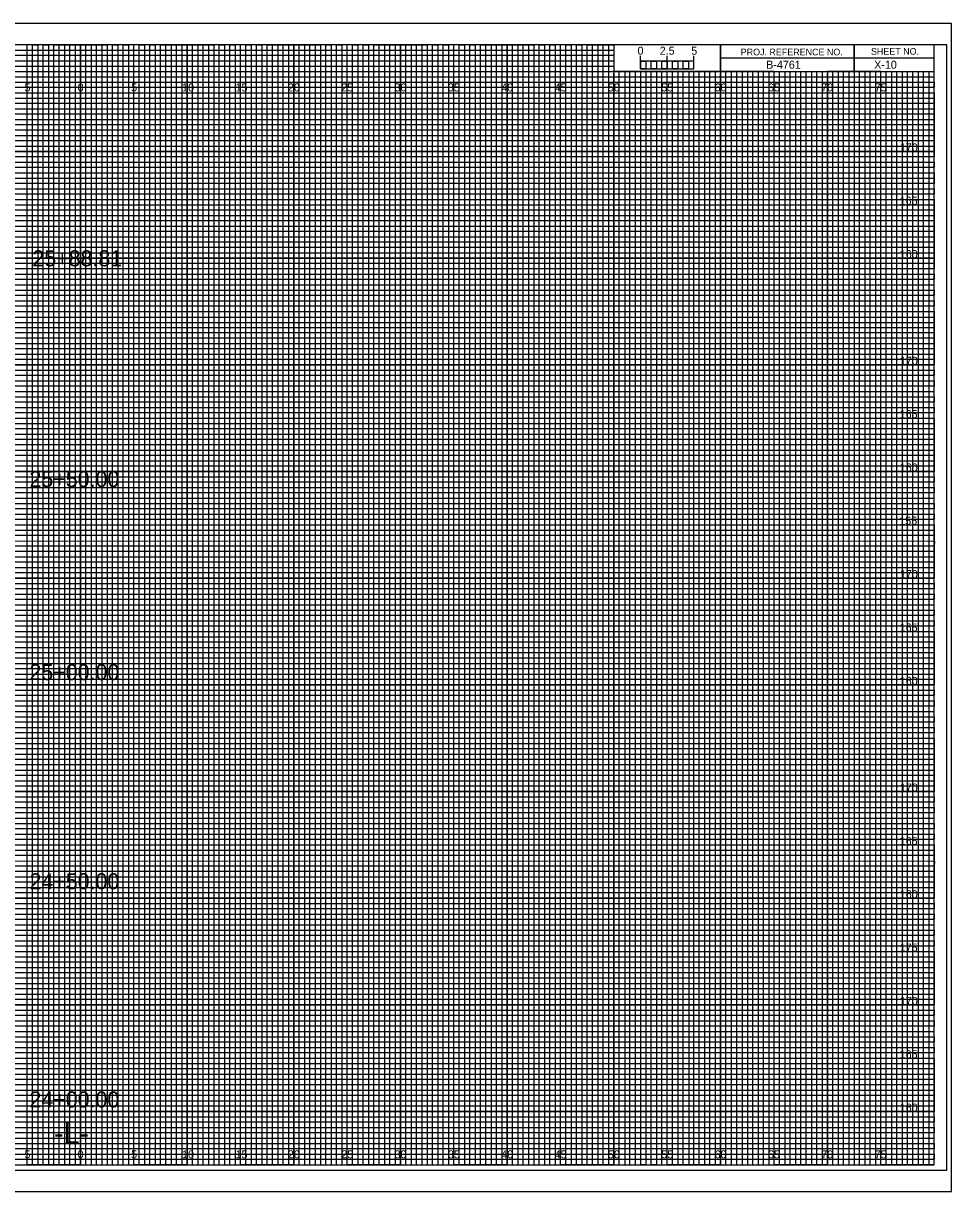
# Model space of a CAD drawing. Extents: x -7 to 162, y 878 to 987.
# Drawn here: x 74.6 to 161.7, y 877.5 to 987 of the extents above; entities that cross this region are included whole.
import ezdxf

# ---------------------------------------------------------------- set-up
doc = ezdxf.new("R2010")
doc.units = 0
for name, color, linetype in [('Prop XS Alignment Label', 7, 'Continuous'), ('Prop XS Bar Scale Labels', 7, 'Continuous'), ('Prop XS Elevation Labels', 7, 'Continuous'), ('Prop XS Offset Labels', 7, 'Continuous'), ('Prop XS Project Number', 7, 'Continuous'), ('Prop XS Sheet Number', 7, 'Continuous'), ('Prop XS Station Labels', 7, 'Continuous'), ('Sheet Cross Section CELL', 7, 'Continuous'), ('Sheet Cross Section Grid Major CELL', 7, 'Continuous'), ('Sheet Cross Section Grid Middle CELL', 7, 'Continuous'), ('Sheet Cross Section Grid Minor 1 CELL', 7, 'Continuous'), ('Sheet Cross Section Grid Minor 2 CELL', 7, 'Continuous'), ('Sheet Cross Section Scale CELL', 7, 'Continuous'), ('Sheet Cutting Line CELL', 7, 'Continuous'), ('Sheet DOT Grid CELL', 7, 'Continuous'), ('Sheet Plot Border Inside CELL', 7, 'Continuous'), ('Sheet Plot Border Outside CELL', 7, 'Continuous')]:
    doc.layers.add(name, color=color, linetype=linetype)

msp = doc.modelspace()

# ---------------------------------------------------------------- linework, layer by layer
at = {"layer": 'Sheet Cross Section CELL'}
for p, q in [((152.5, 985), (152.5, 982.5)), ((152.5, 982.5), (152.5, 985)), ((160, 983.75), (140, 983.75)), ((140, 983.75), (140, 982.5)), ((140, 982.5), (160, 982.5))]:
    msp.add_line(p, q, dxfattribs=at)
for points in [[(160, 985), (0, 985), (0, 880), (160, 880)], [(140, 985), (130, 985), (130, 982.51), (140, 982.51)], [(160, 985), (140, 985), (140, 982.5), (160, 982.5)]]:
    msp.add_lwpolyline(points, close=True, dxfattribs=at)
at = {"layer": 'Sheet Cross Section Grid Major CELL'}
for p, q in [((75, 985), (70, 985)), ((75, 880), (75, 985)), ((85, 985), (80, 985)), ((80, 985), (80, 880)), ((85, 880), (85, 985)), ((95, 985), (90, 985)), ((90, 985), (90, 880)), ((95, 880), (95, 985)), ((105, 985), (100, 985)), ((100, 985), (100, 880)), ((105, 880), (105, 985)), ((115, 985), (110, 985)), ((110, 985), (110, 880)), ((115, 880), (115, 985)), ((125, 985), (120, 985)), ((120, 985), (120, 880)), ((125, 880), (125, 985)), ((130, 985), (130, 880)), ((135, 880), (135, 982.5)), ((145, 982.5), (140, 982.5)), ((140, 982.5), (140, 880)), ((145, 880), (145, 982.5)), ((155, 982.5), (150, 982.5)), ((150, 982.5), (150, 880)), ((155, 880), (155, 982.5)), ((80, 880), (75, 880)), ((90, 880), (85, 880)), ((100, 880), (95, 880)), ((110, 880), (105, 880)), ((120, 880), (115, 880)), ((130, 880), (125, 880)), ((140, 880), (135, 880)), ((150, 880), (145, 880)), ((160, 880), (155, 880)), ((160, 880), (160, 880))]:
    msp.add_line(p, q, dxfattribs=at)
for points in [[(0, 980), (160, 980), (160, 975), (0, 975)], [(0, 970), (160, 970), (160, 965), (0, 965)], [(0, 960), (160, 960), (160, 955), (0, 955)], [(0, 950), (160, 950), (160, 945), (0, 945)], [(0, 940), (160, 940), (160, 935), (0, 935)], [(0, 930), (160, 930), (160, 925), (0, 925)], [(0, 920), (160, 920), (160, 915), (0, 915)], [(0, 910), (160, 910), (160, 905), (0, 905)], [(0, 900), (160, 900), (160, 895), (0, 895)], [(0, 890), (160, 890), (160, 885), (0, 885)]]:
    msp.add_lwpolyline(points, dxfattribs=at)
at = {"layer": 'Sheet Cross Section Grid Middle CELL'}
for points in [[(72.5, 880), (77.5, 880), (77.5, 985), (82.5, 985), (82.5, 880), (87.5, 880), (87.5, 985), (92.5, 985), (92.5, 880), (97.5, 880), (97.5, 985), (102.5, 985), (102.5, 880), (107.5, 880), (107.5, 985), (112.5, 985), (112.5, 880), (117.5, 880), (117.5, 985), (122.5, 985), (122.5, 880), (127.5, 880), (127.5, 985), (129.97, 985), (130, 985), (130, 982.5), (132.5, 982.5), (132.5, 880), (137.5, 880), (137.5, 982.5), (142.5, 982.5), (142.5, 880), (147.5, 880), (147.5, 982.5), (152.5, 982.5), (152.5, 880), (157.5, 880), (157.5, 982.5)], [(0, 982.5), (137.5, 982.5)], [(0, 972.5), (160, 972.5), (160, 977.5), (0, 977.5)], [(0, 962.5), (160, 962.5), (160, 967.5), (0, 967.5)], [(0, 952.5), (160, 952.5), (160, 957.5), (0, 957.5)], [(0, 942.5), (160, 942.5), (160, 947.5), (0, 947.5)], [(0, 932.5), (160, 932.5), (160, 937.5), (0, 937.5)], [(0, 922.5), (160, 922.5), (160, 927.5), (0, 927.5)], [(0, 912.5), (160, 912.5), (160, 917.5), (0, 917.5)], [(0, 902.5), (160, 902.5), (160, 907.5), (0, 907.5)], [(0, 892.5), (160, 892.5), (160, 897.5), (0, 897.5)], [(0, 882.5), (160, 882.5), (160, 887.5), (0, 887.5)]]:
    msp.add_lwpolyline(points, dxfattribs=at)
at = {"layer": 'Sheet Cross Section Grid Minor 1 CELL'}
for p, q in [((0, 984.5), (130, 984.5)), ((130, 984.5), (130, 983.99)), ((130, 983.99), (0, 983.99)), ((0, 983.5), (130, 983.5)), ((130, 983.5), (130, 982.95)), ((130, 982.95), (0, 982.95)), ((0, 982), (160, 982))]:
    msp.add_line(p, q, dxfattribs=at)
for points in [[(0, 981.5), (135, 981.5), (160, 981.5), (160, 981), (0, 981)], [(0, 980.5), (160, 980.5), (160, 979.5), (0, 979.5)], [(0, 979), (160, 979), (160, 978.5), (0, 978.49)], [(0, 978), (160, 978), (160, 977), (0, 977)], [(0, 976.5), (160, 976.5), (160, 976), (0, 976)], [(0, 975.5), (160, 975.5), (160, 974.5), (0, 974.5)], [(0, 974), (160, 974), (160, 973.5), (0, 973.5)], [(0, 973), (160, 973), (160, 972), (0, 972)], [(0, 971.5), (160, 971.5), (160, 971), (0, 971)], [(0, 970.5), (160, 970.5), (160, 969.5), (0, 969.5)], [(0, 969), (160, 969), (160, 968.5), (0, 968.5)], [(0, 968), (160, 968), (160, 966.98), (160, 966.5), (160, 966), (0, 966)], [(0, 967), (160, 967), (160, 966.5), (0, 966.5)], [(0, 965.5), (160, 965.5), (160, 964.5), (0, 964.51)], [(0, 964.51), (160, 964.5), (160, 964), (0, 964)], [(0, 963.5), (160, 963.5), (160, 963), (0, 963)], [(0, 962), (160, 962), (160, 961.5), (0, 961.5)], [(0, 961), (160, 961), (160, 960.5), (0, 960.5)], [(-0.04, 959.45), (160, 959.45), (160, 958.94), (-0.04, 958.94)], [(0, 958.5), (160, 958.5), (160, 958), (0, 958)], [(0, 957), (160, 957), (160, 956.5), (0, 956.5)], [(0, 956), (160, 956), (160, 955.5), (0, 955.5)], [(0, 954.5), (160, 954.5), (160, 954), (0, 954)], [(0, 953.5), (160, 953.5), (160, 953), (0, 953)], [(0, 952), (160, 952), (160, 951.5), (0, 951.5)], [(0, 951), (160, 951), (160, 950.5), (0, 950.5)], [(0, 949.5), (160, 949.5), (160, 948.99), (0, 949)], [(0, 948.5), (160, 948.5), (160, 948), (0, 948)], [(0, 947), (160, 947), (160, 946.5), (0, 946.5)], [(0, 946), (160, 946), (160, 945.5), (0, 945.5)], [(0, 944.5), (160, 944.5), (160, 944), (0, 944)], [(0, 943.5), (160, 943.5), (160, 943), (0, 943)], [(0, 942), (160, 942), (160, 941.5), (0, 941.5)], [(0, 941), (160, 941), (160, 940.5), (0, 940.5)], [(0, 939.5), (160, 939.5), (160, 939), (0, 939)], [(0, 938.5), (160.03, 938.46), (160, 938), (0, 938)], [(0, 937), (160, 937), (160, 936.5), (0, 936.5)], [(0, 936), (160, 936), (160, 935.5), (0, 935.5)], [(0, 934.5), (160, 934.5), (160, 934), (0, 934)], [(0, 933.5), (160, 933.5), (160, 933), (0, 933)], [(0, 932), (160, 932), (160, 931.5), (0, 931.5)], [(0, 931), (160, 931), (160, 930.5), (0, 930.5)], [(0, 929.5), (160, 929.5), (160, 929), (0, 929)], [(0, 928.5), (160, 928.5), (160, 928), (0, 928)], [(0, 927), (160, 927), (160, 926.5), (0, 926.5)], [(0, 926), (160, 926), (160, 925.5), (0, 925.5)], [(0, 924.5), (160, 924.5), (160, 924), (0, 924)], [(0, 923.5), (160, 923.5), (160, 923), (0, 923)], [(0, 922), (160, 922), (160, 921.5), (0, 921.5)], [(0, 921), (160, 921), (160, 920.5), (0, 920.5)], [(0, 919.5), (160, 919.5), (160, 918.99), (0, 919)], [(0, 918.5), (160, 918.5), (160, 918), (0, 918)], [(0, 917), (160, 917), (160, 916.5), (0, 916.5)], [(0, 916), (160, 916), (160, 915.5), (0, 915.5)], [(0, 914.5), (160, 914.5), (160, 914), (0, 914)], [(0, 913.5), (160, 913.5), (160, 913), (0, 913)], [(0, 912), (160, 912), (160, 911.5), (0, 911.5)], [(0, 911), (160, 911), (160, 910.5), (0, 910.5)], [(0, 909.5), (160, 909.5), (160, 909), (0, 909)], [(0, 908.5), (160.03, 908.46), (160, 908), (0, 908)], [(0, 907), (160, 907), (160, 906.5), (0, 906.5)], [(0, 906), (160, 906), (160, 905.5), (0, 905.5)], [(0, 904.5), (160, 904.5), (160, 904), (0, 904)], [(0, 903.5), (160, 903.5), (160, 903), (0, 903)], [(0, 902), (160, 902), (160, 901.5), (0, 901.5)], [(0, 901), (160, 901), (160, 900.5), (0, 900.5)], [(0, 899.5), (160, 899.5), (160, 899), (0, 899)], [(0, 898.5), (160, 898.5), (160, 898), (0, 898)], [(0, 897), (160, 897), (160, 896.5), (0, 896.5)], [(0, 896), (160, 896), (160, 895.5), (0, 895.5)], [(0, 894.5), (160, 894.5), (160, 894), (0, 894)], [(0, 893.5), (160, 893.5), (160, 893), (0, 893)], [(0, 892), (160, 892), (160, 891.5), (0, 891.5)], [(0, 891), (160, 891), (160, 890.5), (0, 890.5)], [(0, 889.5), (160, 889.5), (160, 889), (0, 889)], [(0, 888.5), (160, 888.5), (160, 888), (0, 888)], [(0, 887), (160, 887), (160, 886.5), (0, 886.5)], [(0, 886), (160, 886), (160, 885.5), (0, 885.5)], [(0, 884.5), (160, 884.5), (160, 884), (0, 884)], [(0, 883.5), (160, 883.5), (160, 883), (0, 883)], [(0, 882), (160, 882), (160, 881.5), (0, 881.5)], [(0, 881), (160, 881), (160, 880.5), (0, 880.5)]]:
    msp.add_lwpolyline(points, dxfattribs=at)
at = {"layer": 'Sheet Cross Section Grid Minor 2 CELL'}
for p, q in [((133.5, 982.5), (133, 982.5)), ((133, 982.5), (133, 880)), ((133.5, 880), (133.5, 982.5)), ((134.5, 982.5), (134, 982.5)), ((134, 982.5), (134, 880)), ((134.5, 880), (134.5, 982.5)), ((133, 880), (132.5, 880)), ((134, 880), (133.5, 880))]:
    msp.add_line(p, q, dxfattribs=at)
for points in [[(75, 880), (75.5, 880), (75.5, 985), (76, 985), (76, 880)], [(76, 880), (76.5, 880), (76.5, 985), (77, 985), (77, 880)], [(77.5, 880), (78, 880), (78, 985), (78.5, 985), (78.5, 880)], [(78.5, 880), (79, 880), (79, 985), (79.5, 985), (79.5, 880)], [(80, 880), (80.5, 880), (80.5, 985), (81, 985), (81, 880)], [(81, 880), (81.5, 880), (81.5, 985), (82, 985), (82, 880)], [(82.5, 880), (83, 880), (83, 985), (83.5, 985), (83.5, 880)], [(83.5, 880), (84, 880), (84, 985), (84.5, 985), (84.5, 880)], [(85, 880), (85.5, 880), (85.5, 985), (86, 985), (86, 880)], [(86, 880), (86.5, 880), (86.5, 985), (87, 985), (87, 880)], [(87.5, 880), (88, 880), (88, 985), (88.5, 985), (88.5, 880)], [(88.5, 880), (89, 880), (89, 985), (89.5, 985), (89.5, 880)], [(90, 880), (90.5, 880), (90.5, 985), (91, 985), (91, 880)], [(91, 880), (91.5, 880), (91.5, 985), (92, 985), (92, 880)], [(92.5, 880), (93, 880), (93, 985), (93.5, 985), (93.5, 880)], [(93.5, 880), (94, 880), (94, 985), (94.5, 985), (94.5, 880)], [(95, 880), (95.5, 880), (95.5, 985), (96, 985), (96, 880)], [(96, 880), (96.5, 880), (96.5, 985), (97, 985), (97, 880)], [(97.5, 880), (98, 880), (98, 985), (98.5, 985), (98.5, 880)], [(98.5, 880), (99, 880), (99, 985), (99.5, 985), (99.5, 880)], [(100, 880), (100.5, 880), (100.5, 985), (101, 985), (101, 880)], [(101, 880), (101.5, 880), (101.5, 985), (102, 985), (102, 880)], [(102.5, 880), (103, 880), (103, 985), (103.5, 985), (103.5, 880)], [(103.5, 880), (104, 880), (104, 985), (104.5, 985), (104.5, 880)], [(105, 880), (105.5, 880), (105.5, 985), (106, 985), (106, 880)], [(106, 880), (106.5, 880), (106.5, 985), (107, 985), (107, 880)], [(107.5, 880), (108, 880), (108, 985), (108.5, 985), (108.5, 880)], [(108.5, 880), (109, 880), (109, 985), (109.5, 985), (109.5, 880)], [(110, 880), (110.5, 880), (110.5, 985), (111, 985), (111, 880)], [(111, 880), (111.5, 880), (111.5, 985), (112, 985), (112, 880)], [(112.5, 880), (113, 880), (113, 985), (113.5, 985), (113.5, 880)], [(113.5, 880), (114, 880), (114, 985), (114.5, 985), (114.5, 880)], [(115, 880), (115.5, 880), (115.5, 985), (116, 985), (116, 880)], [(116, 880), (116.5, 880), (116.5, 985), (117, 985), (117, 880)], [(117.5, 880), (118, 880), (118, 985), (118.5, 985), (118.5, 880)], [(118.5, 880), (119, 880), (119, 985), (119.5, 985), (119.5, 880)], [(120, 880), (120.5, 880), (120.5, 985), (121, 985), (121, 880)], [(121, 880), (121.5, 880), (121.5, 985), (122, 985), (122, 880)], [(122.5, 880), (123, 880), (123, 985), (123.5, 985), (123.5, 880)], [(123.5, 880), (124, 880), (124, 985), (124.5, 985), (124.5, 880)], [(125, 880), (125.5, 880), (125.5, 985), (126, 985), (126, 880)], [(126, 880), (126.5, 880), (126.5, 985), (127, 985), (127, 880)], [(127.5, 880), (128, 880), (128, 985), (128.5, 985), (128.5, 880)], [(128.5, 880), (129, 880), (129, 985), (129.5, 985), (129.5, 880)], [(130, 880), (130.5, 880), (130.5, 982.5), (131.01, 982.5), (131.01, 880)], [(131, 880), (131.5, 880), (131.5, 982.5), (132, 982.5), (132, 880)], [(135, 880), (135.49, 880), (135.49, 982.5), (136, 982.5), (136, 880)], [(136, 880), (136.5, 880), (136.5, 982.5), (137.03, 982.5), (137.03, 880)], [(137.5, 880), (138, 880), (138, 982.5), (138.5, 982.5), (138.5, 880)], [(138.5, 880), (139, 880), (139, 982.5), (139.5, 982.5), (139.5, 880)], [(140, 880), (140.5, 880), (140.5, 982.5), (141, 982.5), (141, 880)], [(141, 880), (141.5, 880), (141.5, 982.5), (142, 982.5), (142, 880)], [(142.5, 880), (143, 880), (143, 982.5), (143.5, 982.5), (143.5, 880)], [(143.5, 880), (144, 880), (144, 982.5), (144.5, 982.5), (144.5, 880)], [(145, 880), (145.5, 880), (145.5, 982.5), (146, 982.5), (146, 880)], [(146, 880), (146.5, 880), (146.5, 982.5), (147, 982.5), (147, 880)], [(147.5, 880), (148, 880), (148, 982.5), (148.5, 982.5), (148.5, 880)], [(148.5, 880), (149, 880), (149, 982.5), (149.5, 982.5), (149.5, 880)], [(150, 880), (150.5, 880), (150.5, 982.5), (151, 982.5), (151, 880)], [(151, 880), (151.5, 880), (151.5, 982.5), (152, 982.5), (152, 880)], [(152.5, 880), (153, 880), (153, 982.5), (153.5, 982.5), (153.5, 880)], [(153.5, 880), (154, 880), (154, 982.5), (154.5, 982.5), (154.5, 880)], [(155, 880), (155.5, 880), (155.5, 982.5), (156, 982.5), (156, 880)], [(156, 880), (156.5, 880), (156.5, 982.5), (157, 982.5), (157, 880)], [(157.5, 880), (158, 880), (158, 982.5), (158.5, 982.5), (158.5, 880)], [(158.5, 880), (159, 880), (159, 982.5), (159.5, 982.5), (159.5, 880)]]:
    msp.add_lwpolyline(points, dxfattribs=at)
at = {"layer": 'Sheet Cross Section Scale CELL'}
for p, q in [((132.5, 982.75), (132.5, 983.95)), ((132.5, 983.45), (132.5, 983.95)), ((135, 982.75), (135, 983.95)), ((137.5, 982.75), (137.5, 983.95)), ((137.5, 983.45), (137.5, 983.95))]:
    msp.add_line(p, q, dxfattribs=at)
for points in [[(137.5, 983.45), (132.5, 983.45), (132.5, 982.75), (137.5, 982.75)], [(132.5, 983.45), (133, 983.45), (133, 982.75), (132.5, 982.75)], [(133.5, 983.45), (134, 983.45), (134, 982.75), (133.5, 982.75)], [(134.5, 983.45), (135, 983.45), (135, 982.75), (134.5, 982.75)], [(135.5, 983.45), (136, 983.45), (136, 982.75), (135.5, 982.75)], [(136.5, 983.45), (137, 983.45), (137, 982.75), (136.5, 982.75)]]:
    msp.add_lwpolyline(points, close=True, dxfattribs=at)
at = {"layer": 'Sheet Cutting Line CELL'}
for p, q in [((161.65, 987), (-6.7, 987)), ((-6.7, 877.5), (161.65, 877.5))]:
    msp.add_line(p, q, dxfattribs=at)
at = {"layer": 'Sheet DOT Grid CELL'}
for p, q in [((75, 880), (75, 985)), ((80, 880), (80, 985)), ((85, 880), (85, 985)), ((90, 880), (90, 985)), ((95, 880), (95, 985)), ((100, 880), (100, 985)), ((105, 880), (105, 985)), ((110, 880), (110, 985)), ((115, 880), (115, 985)), ((120, 880), (120, 985)), ((125, 880), (125, 985)), ((130, 880), (130, 982.34)), ((135, 880), (135, 982.34)), ((140, 880), (140, 982.34)), ((145, 880), (145, 982.34)), ((150, 880), (150, 982.34)), ((155, 880), (155, 982.34)), ((0, 980), (160, 980)), ((0, 975), (160, 975)), ((0, 970), (160, 970)), ((0, 965), (160, 965)), ((0, 960), (160, 960)), ((0, 955), (160, 955)), ((0, 950), (160, 950)), ((0, 945), (160, 945)), ((0, 940), (160, 940)), ((0, 935), (160, 935)), ((0, 930), (160, 930)), ((0, 925), (160, 925)), ((0, 920), (160, 920)), ((0, 915), (160, 915)), ((0, 910), (160, 910)), ((0, 905), (160, 905)), ((0, 900), (160, 900)), ((0, 895), (160, 895)), ((0, 890), (160, 890)), ((0, 885), (160, 885))]:
    msp.add_line(p, q, dxfattribs=at)
at = {"layer": 'Sheet Plot Border Inside CELL'}
msp.add_lwpolyline([(-5.4, 879.5), (161.2, 879.5), (161.2, 985), (-5.4, 985)], close=True, dxfattribs=at)
at = {"layer": 'Sheet Plot Border Outside CELL'}
msp.add_lwpolyline([(-6.7, 877.5), (161.65, 877.5), (161.65, 987), (-6.7, 987)], close=True, dxfattribs=at)

# ---------------------------------------------------------------- texts
at = {"layer": 'Prop XS Alignment Label'}
msp.add_text('-L-', height=2, dxfattribs=at).set_placement((77.53, 882))
at = {"layer": 'Prop XS Bar Scale Labels'}
for s, p in [('2.5', (134.29, 984.06)), ('5', (137.24, 984.06))]:
    msp.add_text(s, height=0.75, dxfattribs=at).set_placement(p)
at = {"layer": 'Prop XS Elevation Labels'}
for s, p in [('170', (156.8, 975)), ('165', (156.78, 970)), ('160', (156.79, 965)), ('170', (156.8, 955)), ('165', (156.78, 950)), ('160', (156.79, 945)), ('155', (156.75, 940)), ('170', (156.8, 935)), ('165', (156.78, 930)), ('160', (156.79, 925)), ('170', (156.8, 915)), ('165', (156.78, 910)), ('160', (156.79, 905)), ('175', (156.79, 900)), ('170', (156.8, 895)), ('165', (156.78, 890)), ('160', (156.79, 885))]:
    msp.add_text(s, height=0.75, dxfattribs=at).set_placement(p)
at = {"layer": 'Prop XS Offset Labels'}
for s, p in [('5', (74.74, 980.62)), ('0', (79.73, 980.62)), ('0', (79.73, 980.62)), ('5', (84.74, 980.62)), ('10', (89.52, 980.62)), ('15', (94.53, 980.62)), ('20', (99.43, 980.62)), ('25', (104.44, 980.62)), ('30', (109.43, 980.62)), ('35', (114.44, 980.62)), ('40', (119.43, 980.62)), ('45', (124.44, 980.62)), ('50', (129.43, 980.62)), ('55', (134.44, 980.62)), ('60', (139.43, 980.62)), ('65', (144.44, 980.62)), ('70', (149.43, 980.62)), ('75', (154.44, 980.62)), ('5', (74.74, 880.62)), ('0', (79.73, 880.62)), ('0', (79.73, 880.62)), ('5', (84.74, 880.62)), ('10', (89.52, 880.62)), ('15', (94.53, 880.62)), ('20', (99.43, 880.62)), ('25', (104.44, 880.62)), ('30', (109.43, 880.62)), ('35', (114.44, 880.62)), ('40', (119.43, 880.62)), ('45', (124.44, 880.62)), ('50', (129.43, 880.62)), ('55', (134.44, 880.62)), ('60', (139.43, 880.62)), ('65', (144.44, 880.62)), ('70', (149.43, 880.62)), ('75', (154.44, 880.62))]:
    msp.add_text(s, height=0.75, dxfattribs=at).set_placement(p)
at = {"layer": 'Prop XS Project Number'}
msp.add_text('B-4761', height=0.75, dxfattribs=at).set_placement((144.27, 982.75))
at = {"layer": 'Prop XS Sheet Number'}
msp.add_text('X-10', height=0.75, dxfattribs=at).set_placement((154.39, 982.75))
at = {"layer": 'Prop XS Station Labels'}
for s, p in [('25+88.81', (75.48, 964.23)), ('25+50.00', (75.21, 943.54)), ('25+00.00', (75.21, 925.44)), ('24+50.00', (75.21, 905.84)), ('24+00.00', (75.21, 885.39))]:
    msp.add_text(s, height=1.5, dxfattribs=at).set_placement(p)
at = {"layer": 'Sheet Cross Section CELL'}
for s, p in [('PROJ. REFERENCE NO.', (141.88, 984)), ('SHEET NO.', (154.09, 984.06))]:
    msp.add_text(s, height=0.625, dxfattribs=at).set_placement(p)
at = {"layer": 'Sheet Cross Section Scale CELL'}
msp.add_text('0', height=0.75, dxfattribs=at).set_placement((132.21, 984.06))

doc.saveas('drawing.dxf')
